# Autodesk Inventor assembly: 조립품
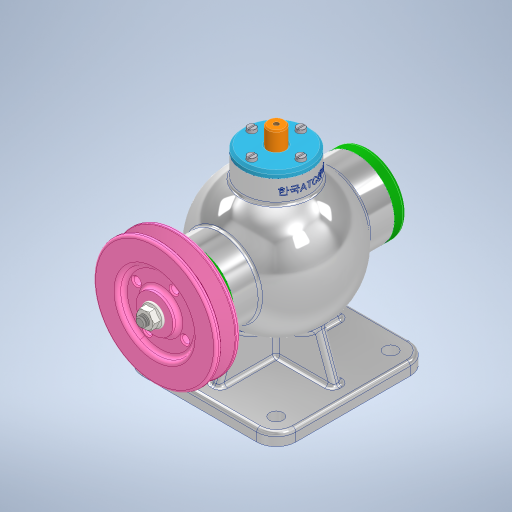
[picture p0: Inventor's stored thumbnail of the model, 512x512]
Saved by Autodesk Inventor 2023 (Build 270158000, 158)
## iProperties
Created: 2023-07
Part Number: 조립품
Document SubType Name: Assembly
Designer: Owner
Author: Owner
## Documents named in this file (15)
- C:\Users\Owner\Desktop\730711V1002\조립품.iam
- C:\Users\Owner\Desktop\730711V1002\본체.ipt
- C:\Users\Owner\Desktop\730711V1002\뒤커버.ipt
- C:\Users\Owner\Desktop\730711V1002\앞커버.ipt
- C:\Users\Owner\Desktop\730711V1002\베어링- 6202.ipt
- KS B 2023 - 6202 - 15 x 35 x 11 - 7.8.ipt
- C:\Users\Owner\Desktop\730711V1002\칼라.ipt
- C:\Users\Owner\Desktop\730711V1002\편심축.ipt
- C:\Users\Owner\Desktop\730711V1002\키 4 x 4 x 12.ipt
- C:\Users\Owner\Desktop\730711V1002\볼트 M4 x 16.ipt
- C:\Users\Owner\Desktop\730711V1002\상부커버.ipt
- C:\Users\Owner\Desktop\730711V1002\볼트 M4 x 12.ipt
- C:\Users\Owner\Desktop\730711V1002\슬라이드.ipt
- C:\Users\Owner\Desktop\730711V1002\V-벨트풀리.ipt
- C:\Users\Owner\Desktop\730711V1002\너트 M8.ipt
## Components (15 placed, 4 different names)
1. KS B 2023 - 6202 - 15 x 35 x 11 - 7.8:4
2. KS B 2023 - 6202 - 15 x 35 x 11 - 7.8:5
3. ISO 4762 M4 x 16:1
4. ISO 4762 M4 x 16:2
5. ISO 4762 M4 x 16:3
6. ISO 4762 M4 x 16:4
7. ISO 4762 M4 x 16:5
8. KS B 1021 - 에 따름 ISO 1207 - 미터 A  M 4 x 12:1
9. KS B 1021 - 에 따름 ISO 1207 - 미터 A  M 4 x 12:2
10. KS B 1021 - 에 따름 ISO 1207 - 미터 A  M 4 x 12:3
11. KS B 1021 - 에 따름 ISO 1207 - 미터 A  M 4 x 12:4
12. ISO 4762 M4 x 16:6
13. ISO 4762 M4 x 16:7
14. ISO 4762 M4 x 16:8
15. V-벨트풀리:1
